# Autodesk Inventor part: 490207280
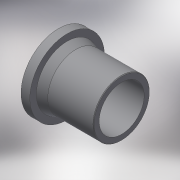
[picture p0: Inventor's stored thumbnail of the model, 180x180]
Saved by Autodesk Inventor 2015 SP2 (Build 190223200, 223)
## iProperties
Created: 2017-07
Part Number: 490207280
Material: Generic
Description: Stub Flange 280
Document SubType Name: Modeling
Designer: Кирилл
Mass: 5750.73 g
Surface Area: 4565.13 cm^2
Volume: 5750.73 cm^3
Density: 1 g/cm^3
Appearance: Default
Author: Кирилл
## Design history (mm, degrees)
derived "490207.ipt"
feature "Solid1::490207.ipt"
tag "TaggingFeature1"
body "Solid1"
other parameters: "d0" = 228, "d1" = 291, "d3" = 224, "d5" = 35, "d17" = 5.6, "d18" = 5.6, "d19" = 5.6, "d21" = 5.6, "d24" = 5.6, "d25" = 5.6, "d26" = 2.8, "d27" = 0, "d32" = 2.8, "L_" = 228, "D_1" = 291, "a_" = 35
